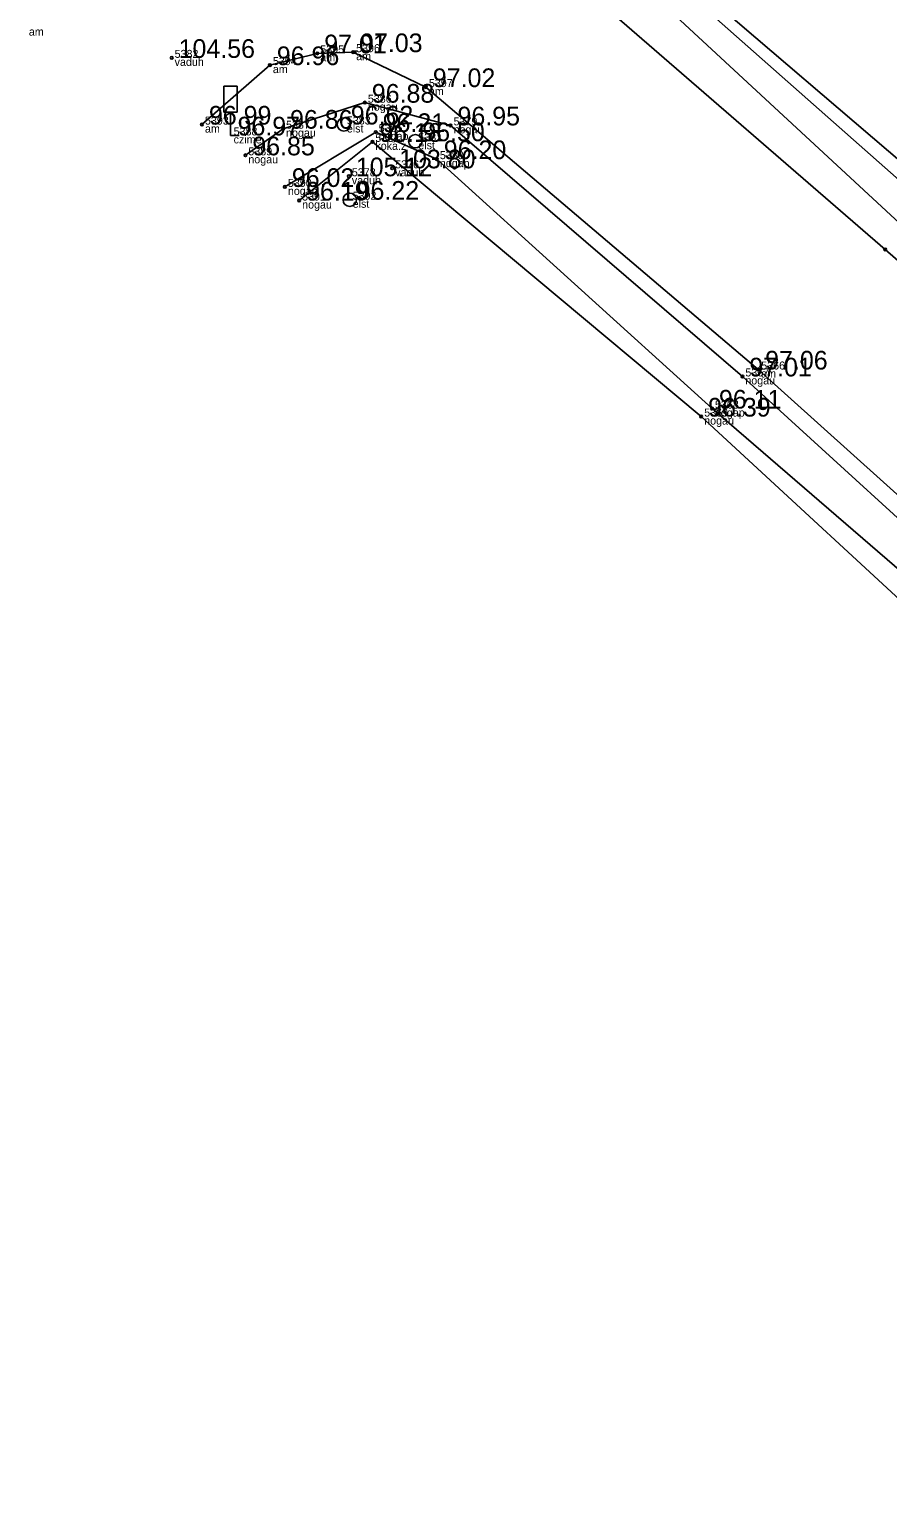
# Model space of a CAD drawing. Extents: x 614911 to 615803, y 262110 to 264311.
# Drawn here: x 615145.2 to 615177.4, y 264177.2 to 264232.1 of the extents above; entities that cross this region are included whole.
import ezdxf

# ---------------------------------------------------------------- set-up
doc = ezdxf.new("R2010")
doc.units = 0
for name, color, linetype in [('Default', 7, 'Continuous'), ('Level 16', 7, 'Continuous'), ('Level 18', 7, 'Continuous'), ('Level 31', 7, 'Continuous'), ('Level 37', 7, 'Continuous'), ('Level 53', 7, 'Continuous'), ('Level 54', 7, 'Continuous'), ('Level 57', 7, 'Continuous'), ('Level 58', 7, 'Continuous')]:
    doc.layers.add(name, color=color, linetype=linetype)

msp = doc.modelspace()

# ---------------------------------------------------------------- linework, layer by layer
at = {"layer": 'Default'}
msp.add_lwpolyline([(615170.431, 264217.616), (615158.106, 264227.914), (615155.36, 264225.714)], dxfattribs=at)
at = {"layer": 'Level 16'}
for p, q in [((615153.038, 264230.002), (615152.538, 264230.002)), ((615152.538, 264229.033), (615152.538, 264230.002)), ((615153.038, 264229.033), (615153.038, 264230.002)), ((615153.038, 264229.033), (615152.538, 264229.033)), ((615152.792, 264229.033), (615152.792, 264228.155)), ((615152.792, 264228.155), (615153.107, 264228.155))]:
    msp.add_line(p, q, dxfattribs=at)
at = {"layer": 'Level 18'}
for centre in [(615157.036, 264228.566), (615159.715, 264227.938), (615157.254, 264225.744)]:
    msp.add_circle(centre, 0.25, dxfattribs=at)
at = {"layer": 'Level 31'}
for points in [[(615169.304, 264234.539), (615179.336, 264225.955), (615189.678, 264217.112), (615189.502, 264216.06), (615187.975, 264215.634), (615178.197, 264224.549), (615167.805, 264234.19)], [(615188.526, 264216.803), (615179.023, 264225.445), (615168.548, 264234.711)], [(615153.344, 264227.409), (615154.758, 264228.407), (615157.823, 264229.383), (615161.036, 264228.531), (615161.036, 264228.531)], [(615161.036, 264228.531), (615171.975, 264219.121), (615181.459, 264210.476)], [(615180.498, 264209.583), (615170.836, 264217.916), (615160.522, 264227.266), (615158.23, 264228.282), (615154.826, 264226.224)], [(615179.987, 264208.794), (615170.431, 264217.616)]]:
    msp.add_lwpolyline(points, dxfattribs=at)
at = {"layer": 'Level 37'}
for points in [[(615187.458, 264215.049), (615177.333, 264223.88), (615166.996, 264232.823), (615164.666, 264235.399), (615164.315, 264239.917), (615166.059, 264245.693), (615168.459, 264248.643), (615163.701, 264252.18)], [(615151.718, 264228.561), (615154.263, 264230.791), (615156.041, 264231.232), (615157.384, 264231.276), (615160.111, 264229.967), (615172.569, 264219.38), (615181.959, 264210.928), (615184.966, 264208.265), (615195.293, 264199.368), (615205.578, 264190.154), (615205.911, 264189.401), (615205.758, 264188.564), (615206.072, 264188.254), (615206.414, 264187.933), (615207.239, 264187.168), (615207.379, 264187.071), (615208.521, 264186.197), (615209.451, 264186.668), (615220.116, 264177.203)]]:
    msp.add_lwpolyline(points, dxfattribs=at)
at = {"layer": 'Level 57'}
for centre in [(615150.581, 264231.062), (615156.041, 264231.232), (615157.384, 264231.276), (615154.263, 264230.791), (615160.111, 264229.967), (615157.823, 264229.383), (615151.718, 264228.561), (615154.758, 264228.407), (615161.036, 264228.531), (615158.106, 264227.914), (615158.23, 264228.282), (615153.344, 264227.409), (615160.522, 264227.266), (615158.848, 264226.922), (615154.826, 264226.224), (615157.223, 264226.624), (615155.36, 264225.714), (615177.333, 264223.88), (615171.975, 264219.121), (615172.569, 264219.38), (615170.836, 264217.916), (615170.431, 264217.616)]:
    msp.add_circle(centre, 0.05, dxfattribs=at)
at = {"layer": 'Level 58'}
for centre in [(615150.581, 264231.062), (615156.041, 264231.232), (615157.384, 264231.276), (615154.263, 264230.791), (615160.111, 264229.967), (615157.823, 264229.383), (615151.718, 264228.561), (615154.758, 264228.407), (615161.036, 264228.531), (615158.106, 264227.914), (615158.23, 264228.282), (615153.344, 264227.409), (615160.522, 264227.266), (615158.848, 264226.922), (615154.826, 264226.224), (615157.223, 264226.624), (615155.36, 264225.714), (615177.333, 264223.88), (615171.975, 264219.121), (615172.569, 264219.38), (615170.836, 264217.916), (615170.431, 264217.616)]:
    msp.add_circle(centre, 0.05, dxfattribs=at)

# ---------------------------------------------------------------- texts
at = {"layer": 'Level 53'}
for s, p in [(' am', (615145.116, 264231.895)), (' am', (615156.041, 264230.932)), (' am', (615157.384, 264230.976)), (' vaduh', (615150.581, 264230.762)), (' am', (615154.263, 264230.491)), (' am', (615160.111, 264229.667)), (' nogau', (615157.823, 264229.083)), (' am', (615151.718, 264228.261)), (' elst', (615157.036, 264228.266)), (' nogau', (615161.036, 264228.231)), (' czime', (615152.792, 264227.855)), (' nogau', (615154.758, 264228.107)), (' koka.z', (615158.106, 264227.614)), (' nogap', (615158.23, 264227.982)), (' elst', (615159.715, 264227.638)), (' nogau', (615153.344, 264227.109)), (' vaduh', (615158.848, 264226.622)), (' nogap', (615160.522, 264226.966)), (' nogap', (615154.826, 264225.924)), (' vaduh', (615157.223, 264226.324)), (' nogau', (615155.36, 264225.414)), (' elst', (615157.254, 264225.444)), (' nogau', (615171.975, 264218.821)), (' am', (615172.569, 264219.08)), (' nogau', (615170.431, 264217.316)), (' nogap', (615170.836, 264217.616))]:
    msp.add_text(s, height=0.3, dxfattribs=at).set_placement(p)
at = {"layer": 'Level 54'}
for s, p in [(' 5382', (615150.581, 264231.062)), (' 5395', (615156.041, 264231.232)), (' 5396', (615157.384, 264231.276)), (' 5394', (615154.263, 264230.791)), (' 5397', (615160.111, 264229.967)), (' 5386', (615157.823, 264229.383)), (' 5393', (615151.718, 264228.561)), (' 5388', (615152.792, 264228.155)), (' 5387', (615154.758, 264228.407)), (' 5383', (615157.036, 264228.566)), (' 5385', (615158.23, 264228.282)), (' 5379', (615161.036, 264228.531)), (' 5384', (615158.106, 264227.914)), (' 5381', (615159.715, 264227.938)), (' 5389', (615153.344, 264227.409)), (' 5380', (615160.522, 264227.266)), (' 5378', (615157.223, 264226.624)), (' 5376', (615158.848, 264226.922)), (' 5390', (615154.826, 264226.224)), (' 5391', (615155.36, 264225.714)), (' 5392', (615157.254, 264225.744)), (' 5366', (615172.569, 264219.38)), (' 5367', (615171.975, 264219.121)), (' 5369', (615170.431, 264217.616)), (' 5368', (615170.836, 264217.916))]:
    msp.add_text(s, height=0.3, dxfattribs=at).set_placement(p)
at = {"layer": 'Level 58'}
for s, p in [(' 104.56', (615150.581, 264231.062)), (' 97.01', (615156.041, 264231.232)), (' 97.03', (615157.384, 264231.276)), (' 96.96', (615154.263, 264230.791)), (' 97.02', (615160.111, 264229.967)), (' 96.88', (615157.823, 264229.383)), (' 96.99', (615151.718, 264228.561)), (' 96.86', (615154.758, 264228.407)), (' 96.62', (615157.036, 264228.566)), (' 96.21', (615158.23, 264228.282)), (' 96.95', (615161.036, 264228.531)), (' 96.97', (615152.792, 264228.155)), (' 96.18', (615158.106, 264227.914)), (' 96.50', (615159.715, 264227.938)), (' 96.85', (615153.344, 264227.409)), (' 96.20', (615160.522, 264227.266)), (' 105.12', (615157.223, 264226.624)), (' 103.80', (615158.848, 264226.922)), (' 96.02', (615154.826, 264226.224)), (' 96.19', (615155.36, 264225.714)), (' 96.22', (615157.254, 264225.744)), (' 97.01', (615171.975, 264219.121)), (' 97.06', (615172.569, 264219.38)), (' 96.11', (615170.836, 264217.916)), (' 96.39', (615170.431, 264217.616))]:
    msp.add_text(s, height=0.7, dxfattribs=at).set_placement(p)

doc.saveas('drawing.dxf')
